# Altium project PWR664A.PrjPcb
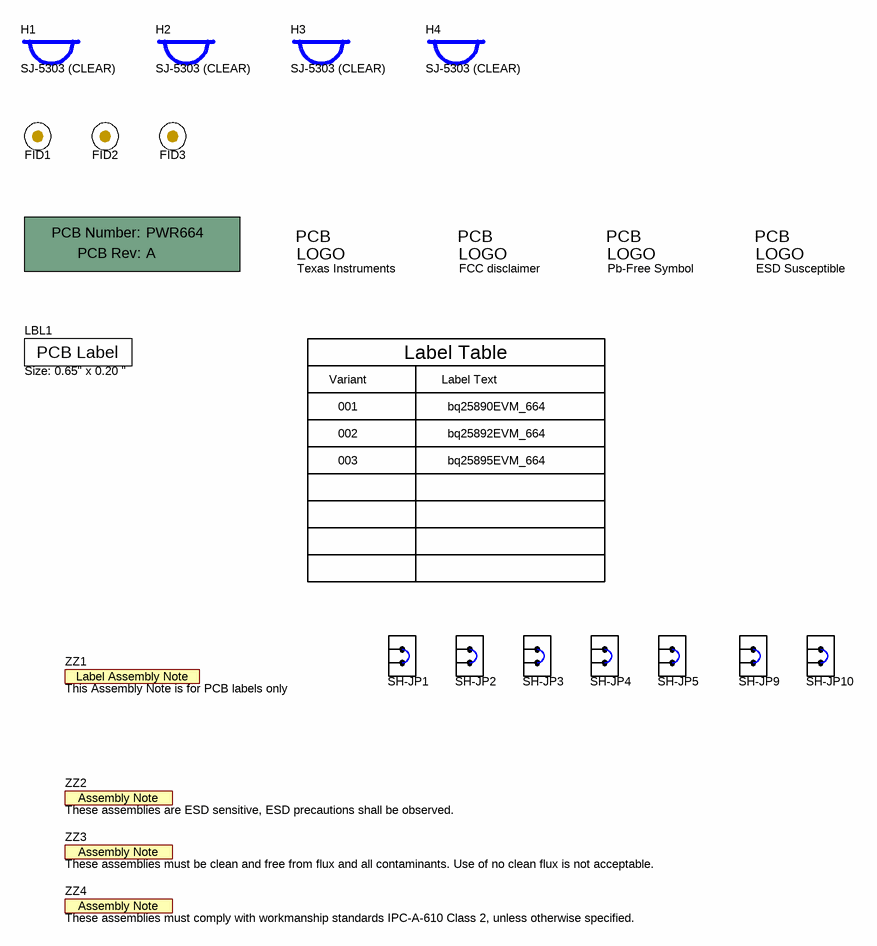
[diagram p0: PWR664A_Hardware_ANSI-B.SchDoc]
CopyrightYear: 2015; PCB_Layout: Alex Ji; PCB_Rev: A; PRJ_Customer: Public Release; PRJ_Engineer: Alex Ji; PRJ_Number: PWR664; PRJ_Title: bq2589xEVM-664; SCH_Rev: A; TechSupport: http://www.ti.com/support
2 sheets, 123 parts. Net scope: flat (ports and power ports of the same name join across sheets).
Board file: PWR664A_PCB.PcbDoc
Sheets:
  PWR664A_Hardware_ANSI-B.SchDoc
  PWR664A_Schematic.SchDoc

## Sheet PWR664A_Hardware_ANSI-B.SchDoc
size 431 x 279 mm; Date: Not shown in title block; ApprovedBy: Not shown in title block; CheckedBy: Not shown in title block; Author: Not shown in title block; CompanyName: Not shown in title block; Engineer: Not shown in title block; Organization: Not shown in title block; Address1: Not shown in title block; Address2: Not shown in title block; Address3: Not shown in title block; Address4: Not shown in title block; DocumentNumber: 1; Revision: Use project parameter SCH_Rev; SheetNumber: 1; SheetTotal: 1; PageSetup: Record=PageOptions¦CenterHorizontal=True¦CenterVertical=True¦PrintScale=1.00¦XCorrection=1.00¦YCorrection=1.00¦PrintKind=0¦BorderSize=5000000¦LeftOffset=0¦BottomOffset=0¦Orientation=2¦PaperLength=1000¦PaperWidth=1000¦Scale=100¦PaperSource=15¦PrintQuality=600¦MediaType=1¦DitherType=10¦PaperKind=Letter¦PrintScaleMode=1

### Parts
!PCB  Printed Circuit Board  (value not drawn)  (mechanical)
FID1  Fiducial  [Fiducial10-20]  (value not drawn)
FID2  Fiducial  [Fiducial10-20]  (value not drawn)
FID3  Fiducial  [Fiducial10-20]  (value not drawn)
H1  SJ-5303 (CLEAR)  [Bumpon_SJ5003Transparent]
H2  SJ-5303 (CLEAR)  [Bumpon_SJ5003Transparent]
H3  SJ-5303 (CLEAR)  [Bumpon_SJ5003Transparent]
H4  SJ-5303 (CLEAR)  [Bumpon_SJ5003Transparent]
LBL1  Size: 0.65" x 0.20 "  [Label_650x200]
Logo1  Texas Instruments  [TI_Stacked_Overlay_Small]  (no BOM)
Logo2  FCC disclaimer  [FCC_disclaimer]  (no BOM)
Logo3  Pb-Free Symbol  [Pb-Free_Overlay_Medium]  (no BOM)
Logo4  ESD Susceptible  [ESD_Overlay_Large]  (no BOM)
SH-JP1  969102-0000-DA  [SNT-100-BK-G]  (value not drawn)
SH-JP2  969102-0000-DA  [SNT-100-BK-G]  (value not drawn)
SH-JP3  969102-0000-DA  [SNT-100-BK-G]  (value not drawn)
SH-JP4  969102-0000-DA  [SNT-100-BK-G]  (value not drawn)
SH-JP5  969102-0000-DA  [SNT-100-BK-G]  (value not drawn)
SH-JP9  969102-0000-DA  [SNT-100-BK-G]  (value not drawn)
SH-JP10  969102-0000-DA  [SNT-100-BK-G]  (value not drawn)
ZZ1  This Assembly Note is for PCB labels only  [AssemblyNoteLabel]  (no BOM)
ZZ2  These assemblies are ESD sensitive, ESD precautions shall be observed.  [AssemblyNote]  (no BOM)
ZZ3  These assemblies must be clean and free from flux and all contaminants. Use of no clean flux is not acceptable.  [AssemblyNote]  (no BOM)
ZZ4  These assemblies must comply with workmanship standards IPC-A-610 Class 2, unless otherwise specified.  [AssemblyNote]  (no BOM)

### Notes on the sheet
- Variant
- 001
- Label Table
- Label Text
- bq25890EVM_664
- 002
- 003
- bq25892EVM_664
- bq25895EVM_664

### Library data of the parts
!PCB = PCB: Manufacturer: Any; PartNumber: PWR655; SymbolCreator: a0412235
FID1-FID3 = Fiducial: Fiducial mark.  There is nothing to buy or mount.; SymbolCreator: codlsc
H1-H4 = SJ-5303 (CLEAR): Bumpon, Hemisphere, 0.44 X 0.20, Clear; Manufacturer: 3M; SymbolCreator: a0412235
LBL1 = THT-14-423-10: Thermal Transfer Printable Labels, 0.650" W x 0.200" H - 10,000 per roll; Manufacturer: Brady; SymbolCreator: a0412235; CompType: Label
Logo1 = TI_Logo: Texas Instrument Corporate Signature; SymbolCreator: codlsc
Logo2 = FCC_disclaimer: SymbolCreator: codlsc
Logo3 = Pb-Free: SymbolCreator: a0412235
Logo4 = ESD_Susceptible: ESD Susceptible Symbol; SymbolCreator: a0412235
SH-JP1-SH-JP5 SH-JP9 SH-JP10 = 969102-0000-DA: Shunt, 100mil, Gold plated, Black; Manufacturer: 3M; Alternate Manufacturer: Samtec; Value: 1x2; Note: You can "mate" this to a header by matching the designator.  i.e. use SH-J3 for header J3
ZZ1 = AssemblyNoteLabel: SymbolCreator: a0412235
ZZ2-ZZ4 = AssemblyNote: SymbolCreator: codlsc

## Sheet PWR664A_Schematic.SchDoc
size 431 x 279 mm; Date: Not shown in title block; ApprovedBy: Not shown in title block; CheckedBy: Not shown in title block; Author: Not shown in title block; CompanyName: Not shown in title block; Engineer: Not shown in title block; Organization: Not shown in title block; Address1: Not shown in title block; Address2: Not shown in title block; Address3: Not shown in title block; Address4: Not shown in title block; DocumentNumber: 1; Revision: Use project parameter SCH_Rev; SheetNumber: 1; SheetTotal: 1; PageSetup: Record=PageOptions¦CenterHorizontal=True¦CenterVertical=True¦PrintScale=0.62¦XCorrection=1.00¦YCorrection=1.00¦PrintKind=0¦BorderSize=5000000¦LeftOffset=0¦BottomOffset=0¦Orientation=2¦PaperLength=1000¦PaperWidth=1000¦Scale=100¦PaperSource=15¦PrintQuality=600¦MediaType=1¦DitherType=10¦PaperKind=Letter¦PrintScaleMode=1
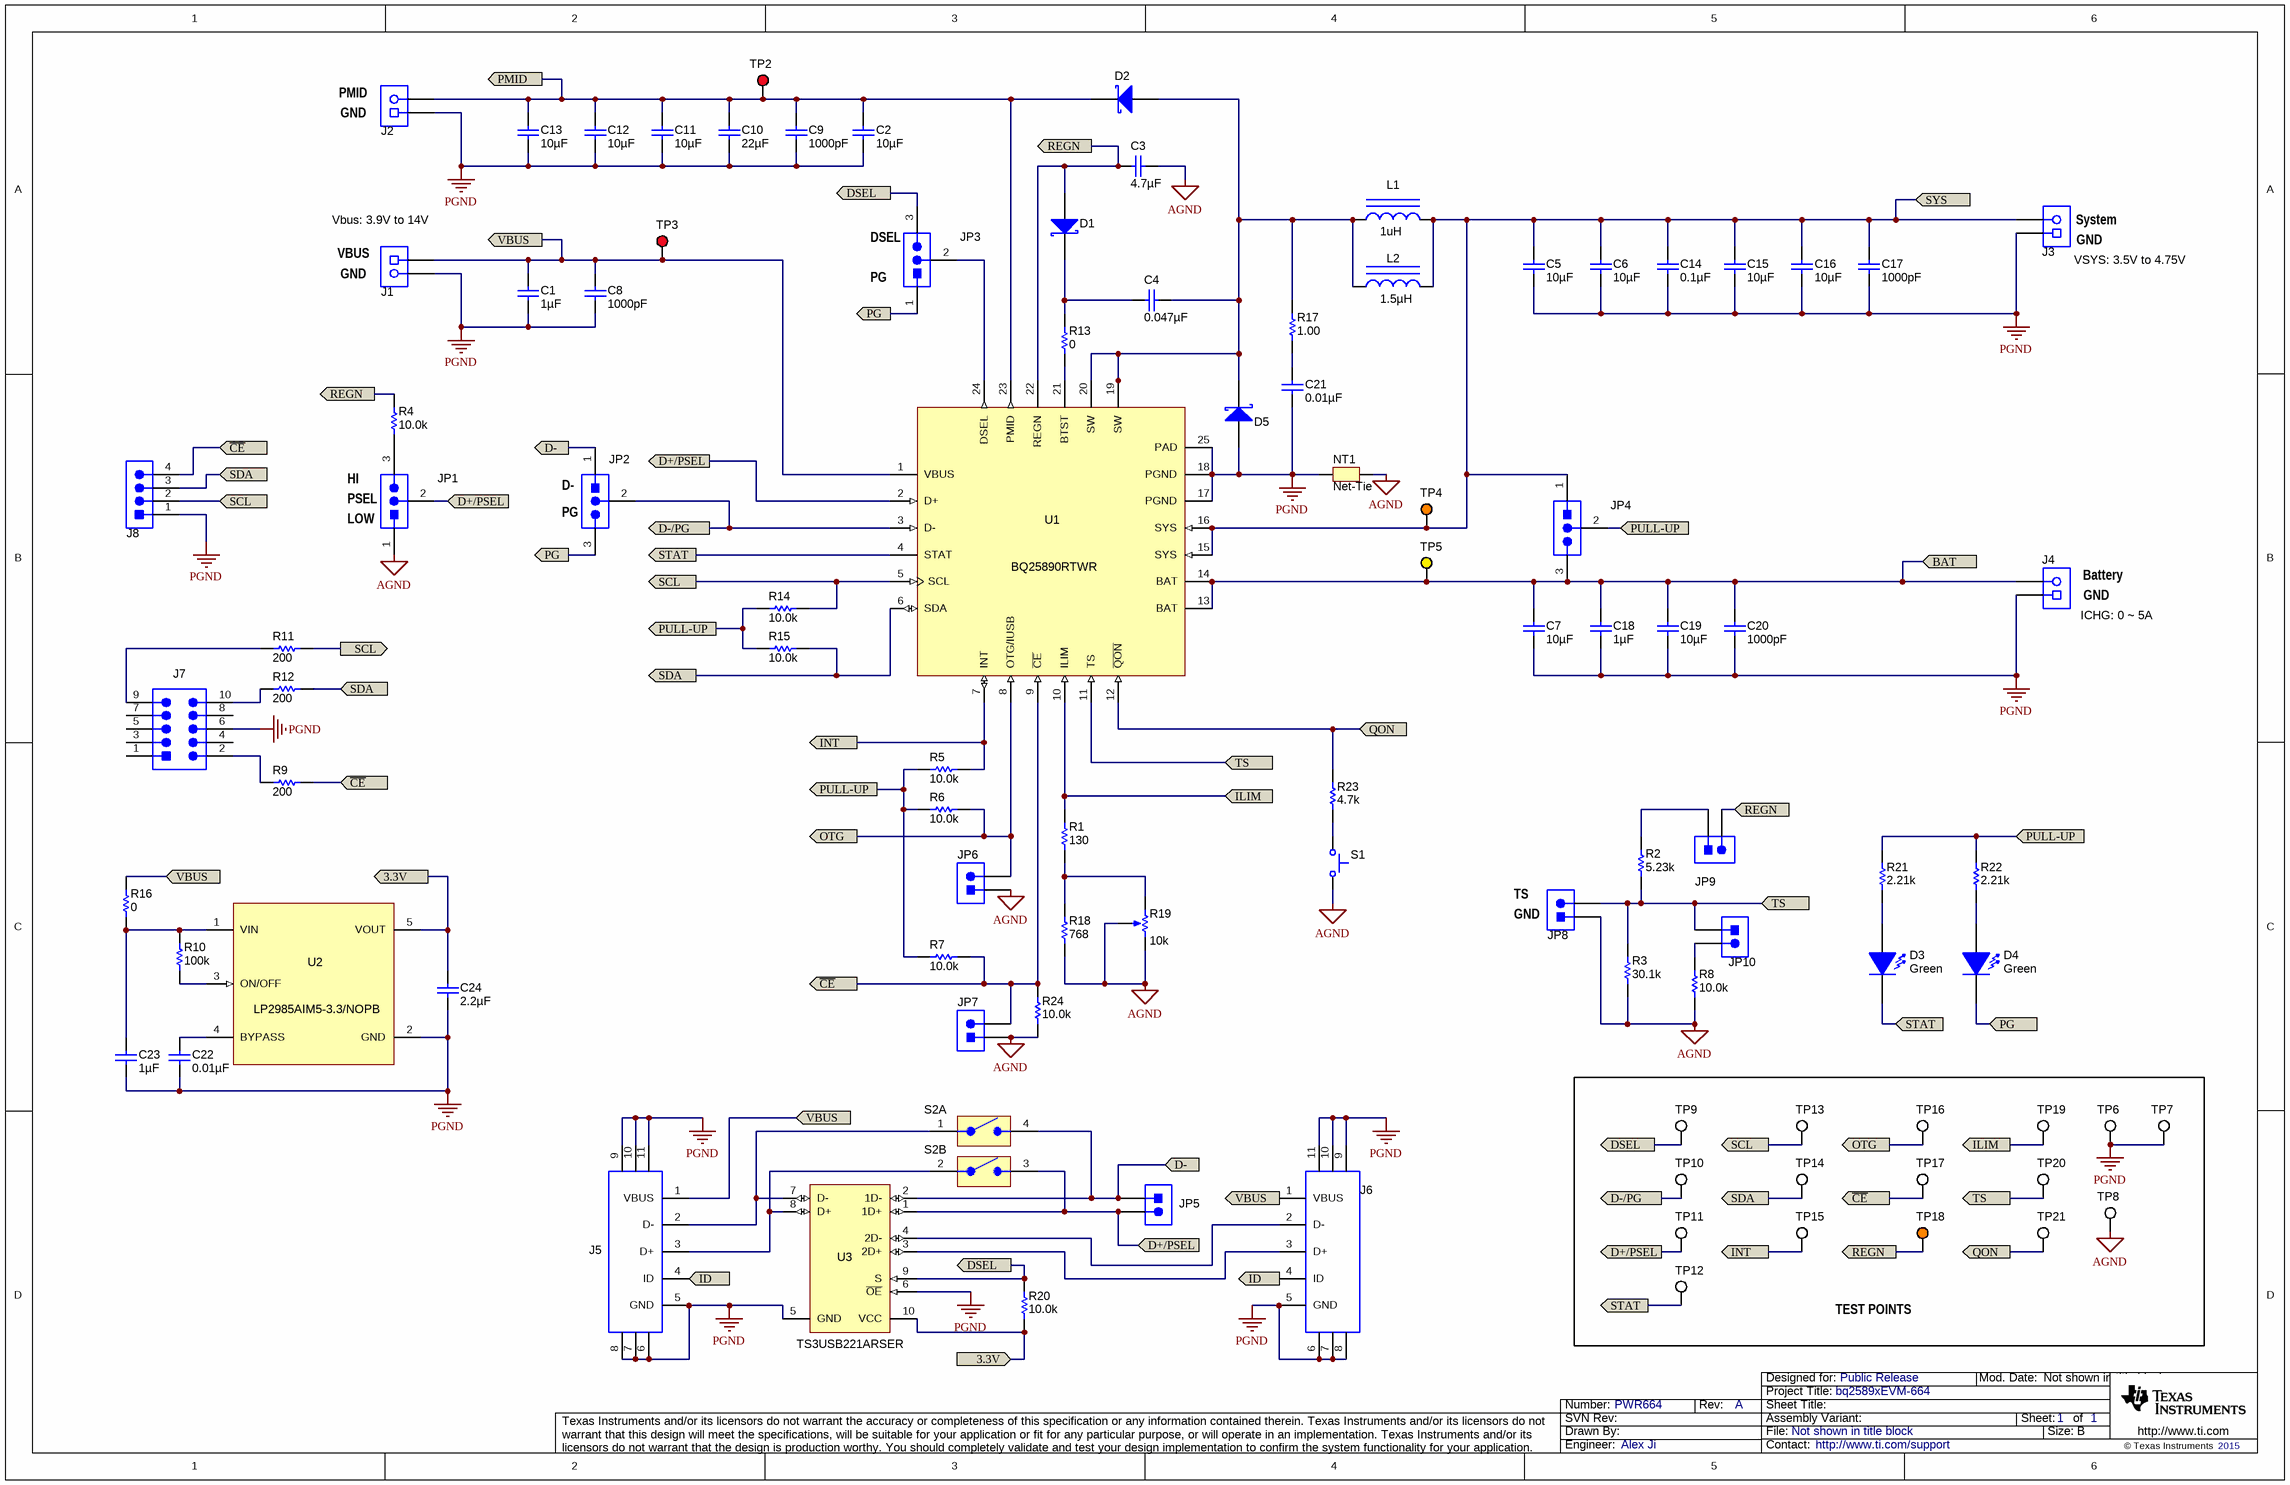
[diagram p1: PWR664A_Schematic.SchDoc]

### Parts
C1  ValueDisplayed: 1µF  [0805L]  (hidden comment: GRM219R71E105KA88D)
C2  ValueDisplayed: 10µF  [0805L]  (hidden comment: C2012X5R1E106K125AB)
C3  ValueDisplayed: 4.7µF  [0603_HV]  (hidden comment: GRM188R61C475KAAJ)
C4  ValueDisplayed: 0.047µF  [0402]  (hidden comment: GRM155R71E473KA88D)
C5  ValueDisplayed: 10µF  [0805L]  (hidden comment: GRM21BR71A106KE51L)
C6  ValueDisplayed: 10µF  [0805L]  (hidden comment: GRM21BR71A106KE51L)
C7  ValueDisplayed: 10µF  [0805L]  (hidden comment: GRM21BR71A106KE51L)
C8  ValueDisplayed: 1000pF  [0402]  (hidden comment: C1005C0G1E102J)
C9  ValueDisplayed: 1000pF  [0402]  (hidden comment: C1005C0G1E102J)
C10  ValueDisplayed: 22µF  [0805L]  (hidden comment: GRM21BR61E226ME44)
C11  ValueDisplayed: 10µF  [0603L]  (hidden comment: GRM188R61E106MA73)
C12  ValueDisplayed: 10µF  [0603L]  (hidden comment: GRM188R61E106MA73)
C13  ValueDisplayed: 10µF  [0603L]  (hidden comment: GRM188R61E106MA73)
C14  ValueDisplayed: 0.1µF  [0603_HV]  (hidden comment: C1608X7R1C104K)
C15  ValueDisplayed: 10µF  [0805L]  (hidden comment: GRM21BR71A106KE51L)
C16  ValueDisplayed: 10µF  [0805L]  (hidden comment: GRM21BR71A106KE51L)
C17  ValueDisplayed: 1000pF  [0402]  (hidden comment: C1005C0G1E102J)
C18  ValueDisplayed: 1µF  [0603_HV]  (hidden comment: C1608X7R1C105K)
C19  ValueDisplayed: 10µF  [0805L]  (hidden comment: GRM21BR71A106KE51L)
C20  ValueDisplayed: 1000pF  [0402]  (hidden comment: C1005C0G1E102J)
C21  ValueDisplayed: 0.01µF  [0402]  (hidden comment: C1005X7R1E103K)
C22  ValueDisplayed: 0.01µF  [0402]  (hidden comment: C1005X7R1E103K)
C23  ValueDisplayed: 1µF  [0603]  (hidden comment: C1608X7R1E105K080AB)
C24  ValueDisplayed: 2.2µF  [0402]  (hidden comment: C1005X5R1A225K050BC)
D1  ZLLS350TA  [SOD-523]  (value not drawn)
D2  NSR10F20NXT5G  [152AD]  (value not drawn)
D3  value Green  [LED_LTST-C190]  (hidden comment: LTST-C190GKT)
D4  value Green  [LED_LTST-C190]  (hidden comment: LTST-C190GKT)
D5  B130LAW-7-F  [SOD-123]  (value not drawn)
J1  1727010  [PhoenixConact_1727010]  (value not drawn)
J2  1727010  [PhoenixConact_1727010]  (value not drawn)
J3  1727010  [PhoenixConact_1727010]  (value not drawn)
J4  1727010  [PhoenixConact_1727010]  (value not drawn)
J5  0473460001  [CONN_47346-0001]  (value not drawn)
J6  0473460001  [CONN_47346-0001]  (value not drawn)
J7  N2510-6002-RB  [CONN_2510-6002]  (value not drawn)
J8  22-05-3041  [CONN_22-05-3041]  (value not drawn)
JP1  PEC03SAAN  [CONN_PEC03SAAN]  (value not drawn)
JP2  PEC03SAAN  [CONN_PEC03SAAN]  (value not drawn)
JP3  PEC03SAAN  [CONN_PEC03SAAN]  (value not drawn)
JP4  PEC03SAAN  [CONN_PEC03SAAN]  (value not drawn)
JP5  PEC02SAAN  [CONN_PEC02SAAN]  (value not drawn)
JP6  PEC02SAAN  [CONN_PEC02SAAN]  (value not drawn)
JP7  PEC02SAAN  [CONN_PEC02SAAN]  (value not drawn)
JP8  PEC02SAAN  [CONN_PEC02SAAN]  (value not drawn)
JP9  PEC02SAAN  [CONN_PEC02SAAN]  (value not drawn)
JP10  PEC02SAAN  [CONN_PEC02SAAN]  (value not drawn)
L1  value 1uH  [IHLP-2020BZ]  (hidden comment: IHLP2020BZER1R0M11)
L2  ValueDisplayed: 1.5µH  [SRP4012]  (hidden comment: SRP4012-1R5M)
NT1  Net-Tie  [Net-Tie_20milWide_60milLong]  (net tie, no BOM)
R1  value 130  [0402]  (hidden comment: CRCW0402130RFKED)
R2  value 5.23k  [0402]  (hidden comment: CRCW04025K23FKED)
R3  value 30.1k  [0402]  (hidden comment: CRCW040230K1FKED)
R4  value 10.0k  [0402]  (hidden comment: CRCW040210K0FKED)
R5  value 10.0k  [0402]  (hidden comment: CRCW040210K0FKED)
R6  value 10.0k  [0402]  (hidden comment: CRCW040210K0FKED)
R7  value 10.0k  [0402]  (hidden comment: CRCW040210K0FKED)
R8  value 10.0k  [0402]  (hidden comment: CRCW040210K0FKED)
R9  value 200  [0402]  (hidden comment: CRCW0402200RFKED)
R10  value 100k  [0402]  (hidden comment: CRCW0402100KFKED)
R11  value 200  [0402]  (hidden comment: CRCW0402200RFKED)
R12  value 200  [0402]  (hidden comment: CRCW0402200RFKED)
R13  value 0  [0402]  (hidden comment: CRCW04020000Z0ED)
R14  value 10.0k  [0402]  (hidden comment: CRCW040210K0FKED)
R15  value 10.0k  [0402]  (hidden comment: CRCW040210K0FKED)
R16  value 0  [0402]  (hidden comment: CRCW04020000Z0ED)
R17  value 1.00  [0805L]  (hidden comment: CRCW08051R00FKEA)
R18  value 768  [0402]  (hidden comment: CRCW0402768RFKED)
R19  value 10k  [TRIM_3266W]  (hidden comment: 3266W-1-103LF)
R20  value 10.0k  [0402]  (hidden comment: CRCW040210K0FKED)
R21  value 2.21k  [0402]  (hidden comment: CRCW04022K21FKED)
R22  value 2.21k  [0402]  (hidden comment: CRCW04022K21FKED)
R23  value 4.7k  [0402]  (hidden comment: CRCW04024K70JNED)
R24  value 10.0k  [0402]  (hidden comment: CRCW040210K0FKED)
S1  KSR221GLFS  [KSR]  (value not drawn)
S2  CVS-02TB  [SW_CVS-02B]  (value not drawn)  (parts A,B of 2)
TP2  5000  [Keystone5000]  (value not drawn)
TP3  5000  [Keystone5000]  (value not drawn)
TP4  5003  [Keystone5003]  (value not drawn)
TP5  5004  [Keystone5004]  (value not drawn)
TP6  5016  [Testpoint_Keystone_Compact]  (value not drawn)
TP7  5016  [Testpoint_Keystone_Compact]  (value not drawn)
TP8  5016  [Testpoint_Keystone_Compact]  (value not drawn)
TP9  5002  [Keystone5002]  (value not drawn)
TP10  5002  [Keystone5002]  (value not drawn)
TP11  5002  [Keystone5002]  (value not drawn)
TP12  5002  [Keystone5002]  (value not drawn)
TP13  5002  [Keystone5002]  (value not drawn)
TP14  5002  [Keystone5002]  (value not drawn)
TP15  5002  [Keystone5002]  (value not drawn)
TP16  5002  [Keystone5002]  (value not drawn)
TP17  5002  [Keystone5002]  (value not drawn)
TP18  5003  [Keystone5003]  (value not drawn)
TP19  5002  [Keystone5002]  (value not drawn)
TP20  5002  [Keystone5002]  (value not drawn)
TP21  5002  [Keystone5002]  (value not drawn)
U1  BQ25890RTWR  [RTW0024H]
U2  LP2985AIM5-3.3/NOPB  [DBV0005A_N]
U3  TS3USB221ARSER  [RSE0010A]

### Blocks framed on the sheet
TEST POINTS: TP6-TP21

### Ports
3.3V, BAT, D+/PSEL, D-, D-/PG, DSEL, ID, ILIM, INT, OTG, PG, PMID, PULL-UP, QON, REGN, SCL, SDA, STAT, SYS, TS, VBUS, ~{CE}

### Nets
AGND: C3.1 JP1.1 JP6.1 JP7.1 JP8.1 NT1.2 R3.1 R8.1 R18.1 R19.2(WIPER) R19.3(CW) R24.1 S1.2 TP8.1
PGND: C1.2 C2.2 C5.2 C6.2 C7.2 C8.2 C9.2 C10.2 C11.2 C12.2 C13.2 C14.2 C15.2 C16.2 C17.2 C18.2 C19.2 C20.2 C21.2 C22.2 C23.2 C24.2 D5.2(A) J1.2 J2.1 J3.1 J4.1 J5.5(GND) J5.6 J5.7 J5.8 J5.9 J5.10 J5.11 J6.5(GND) J6.6 J6.7 J6.8 J6.9 J6.10 J6.11 J7.6 J8.1 NT1.1 TP6.1 TP7.1 U1.17(PGND) U1.18(PGND) U1.25(PAD) U2.2(GND) U3.5(GND) U3.6(~{OE})
3.3V: C24.1 R20.1 U2.5(VOUT) U3.10(VCC) ; port 3.3V
~{CE}: J8.4 JP7.2 R7.2 R9.2 R24.2 TP17.1 U1.9(~{CE}) ; port ~{CE}
BAT: C7.1 C18.1 C19.1 C20.1 J4.2 JP4.3 TP5.1 U1.13(BAT) U1.14(BAT) ; port BAT
D+/PSEL: JP1.2 JP5.2 S2.3 TP11.1 U1.2(D+) U3.1(1D+) ; port D+/PSEL
D-: JP2.1 JP5.1 S2.4 U3.2(1D-) ; port D-
D-/PG: JP2.2 TP10.1 U1.3(D-) ; port D-/PG
DSEL: JP3.3 R20.2 TP9.1 U3.9(S) ; port DSEL
ID: J5.4(ID) J6.4(ID) ; port ID
ILIM: R1.2 TP19.1 U1.10(ILIM) ; port ILIM
INT: R5.2 TP15.1 U1.7(INT) ; port INT
OTG: JP6.2 R6.2 TP16.1 U1.8(OTG/IUSB) ; port OTG
PG: D4.2(K) JP2.3 JP3.1 ; port PG
PMID: C2.1 C9.1 C10.1 C11.1 C12.1 C13.1 D2.1(K) J2.2 TP2.1 U1.23(PMID) ; port PMID
PULL-UP: JP4.2 R5.1 R6.1 R7.1 R14.1 R15.1 R21.2 R22.2 ; port PULL-UP
QON: R23.2 TP21.1 U1.12(~{QON}) ; port QON
REGN: C3.2 D1.2(A) JP9.2 R4.2 TP18.1 U1.22(REGN) ; port REGN
SCL: J8.2 R11.1 R14.2 TP13.1 U1.5(SCL) ; port SCL
SDA: J8.3 R12.2 R15.2 TP14.1 U1.6(SDA) ; port SDA
STAT: D3.2(K) TP12.1 U1.4(STAT) ; port STAT
SYS: C5.1 C6.1 C14.1 C15.1 C16.1 C17.1 J3.2 JP4.1 L1.2 L2.2 TP4.1 U1.15(SYS) U1.16(SYS) ; port SYS
TS: JP8.2 JP10.1 R2.1 R3.2 TP20.1 U1.11(TS) ; port TS
VBUS: C1.1 C8.1 J1.1 J5.1(VBUS) J6.1(VBUS) R16.1 TP3.1 U1.1(VBUS) ; port VBUS
NetC4_1: C4.1 D2.2(A) D5.1(K) L1.1 L2.1 R17.2 U1.19(SW) U1.20(SW)
NetC4_2: C4.2 D1.1(K) R13.2
NetC21_1: C21.1 R17.1
NetC22_1: C22.1 U2.4(BYPASS)
NetC23_1: C23.1 R10.2 R16.2 U2.1(VIN)
NetD3_1: D3.1(A) R21.1
NetD4_1: D4.1(A) R22.1
NetJ5_2: J5.2(D-) S2.1 U3.7(D-)
NetJ5_3: J5.3(D+) S2.2 U3.8(D+)
NetJ6_2: J6.2(D-) U3.4(2D-)
NetJ6_3: J6.3(D+) U3.3(2D+)
NetJ7_2: J7.2 R9.1
NetJ7_9: J7.9 R11.2
NetJ7_10: J7.10 R12.1
NetJP1_3: JP1.3 R4.1
NetJP3_2: JP3.2 U1.24(DSEL)
NetJP9_1: JP9.1 R2.2
NetJP10_2: JP10.2 R8.2
NetR1_1: R1.1 R18.2 R19.1(CCW)
NetR10_1: R10.1 U2.3(ON/OFF)
NetR13_1: R13.1 U1.21(BTST)
NetR23_1: R23.1 S1.1

Not connected (* = marked no-connect by the designer): J7 1 3 4 5 7 8

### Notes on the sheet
- (near J2) PMID
- (near J2) GND
- (near J1) Vbus: 3.9V to 14V
- (near J3) System
- (near J1) VBUS
- (near J1) GND
- (near JP3) DSEL
- (near JP3) PG
- (near J3) GND
- (near J3) VSYS: 3.5V to 4.75V
- HI
- (near JP2) D-
- (near JP1) PSEL
- (near JP1) LOW
- (near JP2) PG
- (near J4) Battery
- (near J4) GND
- (near J4) ICHG: 0 ~ 5A
- (near JP8) TS
- (near JP8) GND

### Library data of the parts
C1 = GRM219R71E105KA88D: CAP, CERM, 1 µF, 25 V, +/- 10%, X7R, 0805; Manufacturer: MuRata; Polarized: N; CompType: Capacitor; Value: 1uF; U/M: EA; Cap_F: 0.000001; Tolerance_%: 10; Value1: Unknown; VDC_V: 25; Value2: 25V; TaMin_C: -55; TaMax_C: 125; Cap_Case: 0805
C2 = C2012X5R1E106K125AB: CAP, CERM, 10uF, 25V, +/-10%, X5R, 0805; Manufacturer: TDK; Polarized: N; CompType: Capacitor; U/M: EA; Cap_F: 0.00001; Tolerance_%: 10; Value1: Unknown; VDC_V: 25; TaMin_C: -55; TaMax_C: 85; Cap_Case: 0805
C3 = GRM188R61C475KAAJ: CAP, CERM, 4.7uF, 16V, +/-10%, X5R, 0603; Manufacturer: MuRata; Polarized: N; CompType: Capacitor; U/M: EA; Cap_F: 0.0000047; Tolerance_%: 10; Value1: Unknown; VDC_V: 16; TaMin_C: -55; TaMax_C: 85; Cap_Case: 0603
C4 = GRM155R71E473KA88D: CAP, CERM, 0.047uF, 25V, +/-10%, X7R, 0402; Manufacturer: MuRata; Polarized: N; CompType: Capacitor; U/M: EA; Cap_F: 0.000000047; Tolerance_%: 10; Value1: Unknown; VDC_V: 25; TaMin_C: -55; TaMax_C: 125
C5-C7 C15 C16 C19 = GRM21BR71A106KE51L: CAP, CERM, 10 µF, 10 V, +/- 10%, X7R, 0805; Manufacturer: MuRata; Polarized: N; CompType: Capacitor; Value: 10uF; U/M: EA; Cap_F: 0.00001; Tolerance_%: 10; ESR_ohm: 0.003; Value1: 0.003 ohm; Value2: 10V; TaMin_C: -55; TaMax_C: 125; Cap_Case: 0805
C8 C9 C17 C20 = C1005C0G1E102J: CAP, CERM, 1000pF, 25V, +/-5%, C0G/NP0, 0402; Manufacturer: TDK; Polarized: N; CompType: Capacitor; U/M: EA; Cap_F: 0.000000001; Tolerance_%: 5; Value1: Unknown; VDC_V: 25; TaMin_C: -55; TaMax_C: 125
C10 = GRM21BR61E226ME44: CAP, CERM, 22 µF, 25 V, +/- 20%, X5R, 0805; Manufacturer: MuRata; Polarized: N; CompType: Capacitor; Value: 22uF; U/M: EA; Cap_F: 0.000022; Tolerance_%: 20; Value1: Unknown; VDC_V: 25; Value2: 25V; TaMin_C: -55; TaMax_C: 85; Cap_Case: 0805
C11-C13 = GRM188R61E106MA73: CAP, CERM, 10uF, 25V, +/-20%, X5R, 0603; Manufacturer: MuRata; Polarized: N; CompType: Capacitor; U/M: EA; Cap_F: 0.00001; Tolerance_%: 20; Value1: Unknown; VDC_V: 25; TaMin_C: -55; TaMax_C: 85; Cap_Case: 0603
C14 = C1608X7R1C104K: CAP, CERM, 0.1uF, 16V, +/-10%, X7R, 0603; Manufacturer: TDK; Polarized: N; CompType: Capacitor; U/M: EA; Cap_F: 0.0000001; Tolerance_%: 10; ESR_Ohm: 0.017; Value1: 0.017 ohm; VDC_V: 16; TaMin_C: -55; TaMax_C: 125; Cap_Case: 0603
C18 = C1608X7R1C105K: CAP, CERM, 1uF, 16V, +/-10%, X7R, 0603; Manufacturer: TDK; Polarized: N; CompType: Capacitor; U/M: EA; Cap_F: 0.000001; Tolerance_%: 10; ESR_Ohm: 0.0057; Value1: 0.0057 ohm; VDC_V: 16; TaMin_C: -55; TaMax_C: 125; Cap_Case: 0603
C21 C22 = C1005X7R1E103K: CAP, CERM, 0.01uF, 25V, +/-10%, X7R, 0402; Manufacturer: TDK; Polarized: N; CompType: Capacitor; U/M: EA; Cap_F: 0.00000001; Tolerance_%: 10; ESR_Ohm: 0.0623; Value1: 0.0623 ohm; VDC_V: 25; TaMin_C: -55; TaMax_C: 125
C23 = C1608X7R1E105K080AB: CAP, CERM, 1uF, 25V, +/-10%, X7R, 0603; Manufacturer: TDK; Polarized: N; CompType: Capacitor; U/M: EA; Cap_F: 0.000001; Tolerance_%: 10; Value1: Unknown; VDC_V: 25; TaMin_C: -55; TaMax_C: 125
C24 = C1005X5R1A225K050BC: CAP, CERM, 2.2uF, 10V, +/-10%, X5R, 0402; Manufacturer: TDK; Polarized: N; CompType: Capacitor; U/M: EA; Cap_F: 0.0000022; Tolerance_%: 10; Value1: Unknown; TaMin_C: -55; TaMax_C: 85
D1 = ZLLS350TA: Diode, Schottky, 40V, 0.38A, SOD-523; Manufacturer: Diodes Inc.; U/M: EA; Vf_V: 0.79; Value2: 0.79V; Io_A: 0.38; Vr_V: 40
D2 = NSR10F20NXT5G: Diode, Schottky, 20 V, 1 A, 1.4x0.6x0.31mm; Manufacturer: ON Semiconductor; U/M: EA; Vf_V: 0.45; Value: 20V; Value1: 1A; Value2: 0.45V; Io_A: 1; Vr_V: 20; TJmax_C: 150
D3 D4 = LTST-C190GKT: LED, Green, SMD; Manufacturer: Lite-On; Vf_V: 2.1; Value2: 2.1V; Io_A: 0.02; Power_TotalModule: 0.1; Value1: 0.1W; U/M: EA
D5 = B130LAW-7-F: Diode, Schottky, 30 V, 1 A, SOD-123; Manufacturer: Diodes Inc.; U/M: EA; Vf_V: 0.38; Value: 30V; Value1: 1A; Value2: 0.38V; Io_A: 1; Vr_V: 30; TJmax_C: 125
J1-J4 = 1727010: Conn Term Block, 2POS, 3.81mm, TH; Manufacturer: Phoenix Contact; SymbolCreator: a0412235; Value: 2x1; CompType: Terminal Block; U/M: EA
J5 J6 = 0473460001: Connector, Receptacle, Micro-USB Type B, R/A, Bottom Mount SMT; Manufacturer: Molex; SymbolCreator: a0411947; U/M: EA
J7 = N2510-6002-RB: Header (shrouded), 100mil, 5x2, High-Temperature, Gold, TH; Manufacturer: 3M; SymbolCreator: a0412235; CompType: Connector; U/M: EA
J8 = 22-05-3041: Header, 100mil, 4x1, R/A, TH; Manufacturer: Molex; SymbolCreator: a0412235; U/M: EA
JP1-JP4 = PEC03SAAN: Header, 100mil, 3x1, Tin plated, TH; Manufacturer: Sullins Connector Solutions; SymbolCreator: a0799628; U/M: EA
JP5-JP10 = PEC02SAAN: Header, 100mil, 2x1, Tin plated, TH; Manufacturer: Sullins Connector Solutions; SymbolCreator: a0412235; U/M: EA
L1 = IHLP2020BZER1R0M11: Inductor, Shielded Drum Core, Powdered Iron, 1uH, 7A, 0.0181 ohm, SMD; Manufacturer: Vishay-Dale; Ind_H: 1.0E-6; ValueDisplayed: 1µH; Imax_A: 7; Irms: 7.5A @ 40C rise; Isat: 7A @ 20% inductance drop; DCR_ohm: 0.0181
L2 = SRP4012-1R5M: Inductor, Flat Wire, Powdered Iron, 1.5 µH, 3 A, 0.05 ohm, SMD; Manufacturer: Bourns; Value: 1.5uH; Ind_H: 1.5E-6; Imax_A: 3; Irms: 3A @ 40C rise; Isat: 5.5A @ 20% inductance drop; DCR_ohm: 0.05; Value2: 3A
NT1 = Net-Tie: Single point connection between nets.; SymbolCreator: codlsc
R1 = CRCW0402130RFKED: RES, 130 ohm, 1%, 0.063W, 0402; Manufacturer: Vishay-Dale; CompType: Resistor; Value_Code: 130R; Tolerance_%: 1; Power_W: 0.063; VDC_V: 50; TempCo: 100 ppm/C; EIA_Code: E96; U/M: EA
R2 = CRCW04025K23FKED: RES, 5.23k ohm, 1%, 0.063W, 0402; Manufacturer: Vishay-Dale; CompType: Resistor; Res_ohm: 5230; Value_Code: 5k23; Tolerance_%: 1; Power_W: 0.063; VDC_V: 50; TempCo: 100 ppm/C; EIA_Code: E96; U/M: EA
R3 = CRCW040230K1FKED: RES, 30.1k ohm, 1%, 0.063W, 0402; Manufacturer: Vishay-Dale; CompType: Resistor; Res_ohm: 30100; Value_Code: 30k1; Tolerance_%: 1; Power_W: 0.063; VDC_V: 50; TempCo: 100 ppm/C; EIA_Code: E96; U/M: EA
R4-R8 R14 R15 R20 R24 = CRCW040210K0FKED: RES, 10.0k ohm, 1%, 0.063W, 0402; Manufacturer: Vishay-Dale; CompType: Resistor; Res_ohm: 10000; Value_Code: 10k0; Tolerance_%: 1; Power_W: 0.063; VDC_V: 50; TempCo: 100 ppm/C; EIA_Code: E96; U/M: EA
R9 R11 R12 = CRCW0402200RFKED: RES, 200 ohm, 1%, 0.063W, 0402; Manufacturer: Vishay-Dale; CompType: Resistor; Value_Code: 200R; Tolerance_%: 1; Power_W: 0.063; VDC_V: 50; TempCo: 100 ppm/C; EIA_Code: E96; U/M: EA
R10 = CRCW0402100KFKED: RES, 100k ohm, 1%, 0.063W, 0402; Manufacturer: Vishay-Dale; CompType: Resistor; Res_ohm: 100000; Tolerance_%: 1; Power_W: 0.063; VDC_V: 50; TempCo: 100 ppm/C; EIA_Code: E96; U/M: EA
R13 R16 = CRCW04020000Z0ED: RES, 0 ohm, 5%, 0.063W, 0402; Manufacturer: Vishay-Dale; CompType: Resistor; Value_Code: 0000; Tolerance_%: 5; Power_W: 0.063; VDC_V: 50; TempCo: 200 ppm/C; EIA_Code: E24; U/M: EA
R17 = CRCW08051R00FKEA: RES, 1.00 ohm, 1%, 0.125W, 0805; Manufacturer: Vishay-Dale; CompType: Resistor; Res_ohm: 1; Value_Code: 1R00; Power_W: 0.125; VDC_V: 150; TempCo: 100 ppm/C; EIA_Code: E96; U/M: EA
R18 = CRCW0402768RFKED: RES, 768 ohm, 1%, 0.063W, 0402; Manufacturer: Vishay-Dale; CompType: Resistor; Value_Code: 768R; Tolerance_%: 1; Power_W: 0.063; VDC_V: 50; TempCo: 100 ppm/C; EIA_Code: E96; U/M: EA
R19 = 3266W-1-103LF: Trimmer, 10k ohm, 0.25W, TH; Manufacturer: Bourns; Sim Note: Enter the Resistance value and the set point into parameter fields.; SymbolCreator: a0412235
R21 R22 = CRCW04022K21FKED: RES, 2.21k ohm, 1%, 0.063W, 0402; Manufacturer: Vishay-Dale; CompType: Resistor; Res_ohm: 2210; Value_Code: 2k21; Tolerance_%: 1; Power_W: 0.063; VDC_V: 50; TempCo: 100 ppm/C; EIA_Code: E96; U/M: EA
R23 = CRCW04024K70JNED: RES, 4.7k ohm, 5%, 0.063W, 0402; Manufacturer: Vishay-Dale; CompType: Resistor; Res_ohm: 4700; Value_Code: 4k70; Tolerance_%: 5; Power_W: 0.063; VDC_V: 50; TempCo: 200 ppm/C; EIA_Code: E24; U/M: EA
S1 = KSR221GLFS: Switch, Normally open, 2.3N force, 200k operations, SMD; Manufacturer: C and K Components; CompType: SPST Switch; U/M: EA
S2 = CVS-02TB: DIP Switch, SPST, 2Pos, Slide, SMT; Manufacturer: Copal Electronics; SymbolCreator: x0208325; VDC_V: 6; SwitchFunction: Off-On; PositionCount: 2; CurrentRating_mA: 100
TP2 TP3 = 5000: Test Point, Miniature, Red, TH; Manufacturer: Keystone; CompType: Test Point Loop; U/M: EA
TP4 TP18 = 5003: Test Point, Miniature, Orange, TH; Manufacturer: Keystone; CompType: Test Point Loop; U/M: EA
TP5 = 5004: Test Point, Miniature, Yellow, TH; Manufacturer: Keystone; CompType: Test Point Loop; U/M: EA
TP6-TP8 = 5016: Test Point, Compact, SMT; Manufacturer: Keystone; CompType: Test Point Loop; U/M: EA
TP9-TP17 TP19-TP21 = 5002: Test Point, Miniature, White, TH; Manufacturer: Keystone; CompType: Test Point Loop; U/M: EA
U1 = BQ25890RTWR: I2C Controlled 5A Single Cell Charger with NVDC Power Path Management and MaxChargeTM High Voltage Adapter Support, RTW0024H; Alternate PartNumber: BQ25890RTWT; Manufacturer: Texas Instruments; SymbolCreator: Altium; CompType: IC; U/M: EA
U2 = LP2985AIM5-3.3/NOPB: Micropower 150 mA Low-Noise Ultra Low-Dropout Regulator in SOT-23 Package, DBV0005A; Alternate Manufacturer: None; Manufacturer: Texas Instruments; SymbolCreator: a0411947; CompType: IC; U/M: EA
U3 = TS3USB221ARSER: ESD Protected,High-Speed USB 2.0 (480-Mbps) 1:2 Multiplexer / Demultiplexer Switch, 1:2 Mux / Demux, 6 ohm RON, 2.5 to 3.3V, -40 to 85 degC, 10-Pin UQFN (RSE), Green (RoHS & no Sb/Br); Manufacturer: Texas Instruments; Alternate Manufacturer: None; Alternate PartNumber: Equivalent; SubFamily: USB Switch; Number of Channels: 2; Architecture: 1; ESD HBM(kV): +/-7; ICC(uA): 30; OFF Time(Max)(ns): 12; Vcc range(V): 2.3 to 3.6; tpd max(ns): 0.25; ron(max)(ohms): 6; RON Mis-match(Max)(Ohms): 0.2; Bandwidth(MHz): 900

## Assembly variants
001: not fitted C8 C9 C10 C11 C12 C13 C14 C15 C16 C17 C18 C19 C20 C21 D1 D2 D5 FID1 FID2 FID3 L2 R7 R17 SH-JP1
002: not fitted C8 C9 C10 C11 C12 C13 C14 C15 C16 C17 C18 C19 C20 C21 D1 D2 D5 FID1 FID2 FID3 L2 R7 R16 R17 SH-JP5; alternate parts U1 -> BQ25892RTWR
003: not fitted C8 C9 C14 C15 C16 C17 C18 C19 C20 C21 D1 D5 FID1 FID2 FID3 L2 R7 R17 SH-JP1; alternate parts L1 -> IHLP2525CZER2R2M01, U1 -> BQ25895RTWR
